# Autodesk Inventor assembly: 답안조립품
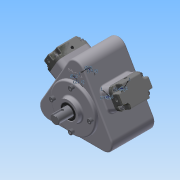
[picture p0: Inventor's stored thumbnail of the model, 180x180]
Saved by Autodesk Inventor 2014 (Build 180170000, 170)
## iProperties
Created: 2015-06
Part Number: 답안조립품
Document SubType Name: Assembly
Designer: MYHOME
Mass: 5318.58 g
Surface Area: 2414.93 cm^2
Volume: 1564.62 cm^3
Density: 3.39928 g/cm^3
Author: MYHOME
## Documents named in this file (20)
- C:\Documents and Settings\MYHOME\바탕 화면\350605V1045\답안조립품.iam
- C:\Documents and Settings\MYHOME\바탕 화면\350605V1045\본체.ipt
- C:\Documents and Settings\MYHOME\바탕 화면\350605V1045\편심축.ipt
- C:\Documents and Settings\MYHOME\바탕 화면\350605V1045\베어링 NA 4904.ipt
- 베어링 NA 4904.ipt
- C:\Documents and Settings\MYHOME\바탕 화면\350605V1045\M6x0.7x20.ipt
- M6x0.7x20.ipt
- C:\Documents and Settings\MYHOME\바탕 화면\350605V1045\앞커버.ipt
- C:\Documents and Settings\MYHOME\바탕 화면\350605V1045\오일실.ipt
- 오일실.ipt
- C:\Documents and Settings\MYHOME\바탕 화면\350605V1045\부시.ipt
- C:\Documents and Settings\MYHOME\바탕 화면\350605V1045\슬라이드.ipt
- C:\Documents and Settings\MYHOME\바탕 화면\350605V1045\헤더커버.ipt
- 헤더커버.ipt
- C:\Documents and Settings\MYHOME\바탕 화면\350605V1045\M4x0.5x16.ipt
- M4x0.5x16.ipt
- C:\Documents and Settings\MYHOME\바탕 화면\350605V1045\9-가변스프링.ipt
- C:\Documents and Settings\MYHOME\바탕 화면\350605V1045\8-가변스프링.ipt
- C:\Documents and Settings\MYHOME\바탕 화면\350605V1045\11-가변스프링.ipt
- C:\Documents and Settings\MYHOME\바탕 화면\350605V1045\10-가변스프링.ipt
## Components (18 placed, 7 different names)
1. 헤더커버:1
2. 헤더커버:2
3. M4x0.5x16:1
4. M4x0.5x16:2
5. M4x0.5x16:3
6. M4x0.5x16:4
7. M4x0.5x16:5
8. M4x0.5x16:6
9. M4x0.5x16:7
10. M4x0.5x16:8
11. 9-가변스프링:1
12. 8-가변스프링:1
13. 11-가변스프링:1
14. 10-가변스프링:1
15. M6x0.7x20:1
16. M6x0.7x20:2
17. M6x0.7x20:3
18. M6x0.7x20:4
